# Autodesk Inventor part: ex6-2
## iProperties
Author: Administrator
Created: 2001-10
Part Number: ex6-2
Document SubType Name: Modeling
Designer: Administrator
Control State: 0
Master: False
Checked Out: False
PropertySet Name: Design Tracking Control
Shininess: 64.0
Angle Display Precision: 2
Document Length Units: 11272
Document Angle Units: 11286
Document Time Units: 11279
Document Mass Units: 11290
Document Length Units Precision: 3
Document Angle Units Precision: 2
Compacted: False
PropertySet Name: _Private Model Information
Density: 0.0
Volumn: 0.0
Area: 0.0
PropertySet Name: Model Information
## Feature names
1. Extrusion1
2. Hole1
3. Hole2
4. Fillet1
